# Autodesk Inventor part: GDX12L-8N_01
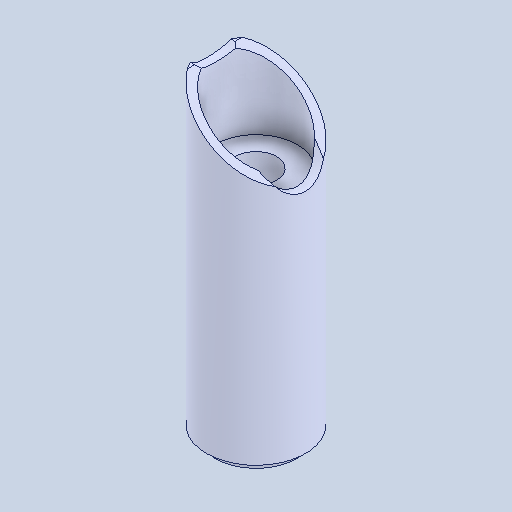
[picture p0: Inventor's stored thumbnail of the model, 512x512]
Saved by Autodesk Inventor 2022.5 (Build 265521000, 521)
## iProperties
Created: 2024-06
Part Number: GDX12L-8N_01
Material: 一般
Document SubType Name: Modeling
Designer: ImaoCorp
Density: 1 g/cm^3
Appearance: 既定
Author: ImaoCorp
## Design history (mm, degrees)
feature "GDX12L-8N_01"
node "ソリッド1"
